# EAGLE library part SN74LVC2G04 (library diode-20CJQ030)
Ti's SN74LVC2G04 DUAL INVERTER GATE Description: This dual inverter is designed for 1.65-V to 5.5-V VCC operation. The SN74LVC2G04 performs the Boolean function Y = /A. NanoStar and NanoFree package technology is a major breakthrough in IC packaging concepts, using the die as the package. This device is fully specified for partial-power-down applications using Ioff. The Ioff circuitry disables the outputs, preventing damaging current backflow through the device when it is powered down. Features: Available in the Texas Instruments NanoStar and NanoFree Packages Supports 5-V VCC Operation Inputs Accept Voltages to 5.5 V Max tpd of 4.1 ns at 3.3 V Low Power Consumption, 10-uA Max ICC ±24-mA Output Drive at 3.3 V Typical VOLP (Output Ground Bounce) less then 0.8 V at VCC = 3.3 V, TA = 25°C Typical VOHV (Output VOH Undershoot) greater then2 V at VCC = 3.3 V, TA = 25°C Ioff Supports Partial-Power-Down Mode Operation Latch-Up Performance Exceeds 100 mA Per JESD 78, Class II ESD Protection Exceeds JESD 22 - 2000-V Human-Body Model (A114-A) - 200-V Machine Model (A115-A) - 1000-V Charged-Device Model (C101) Please send any comments to: messi@users.sourceforge.net
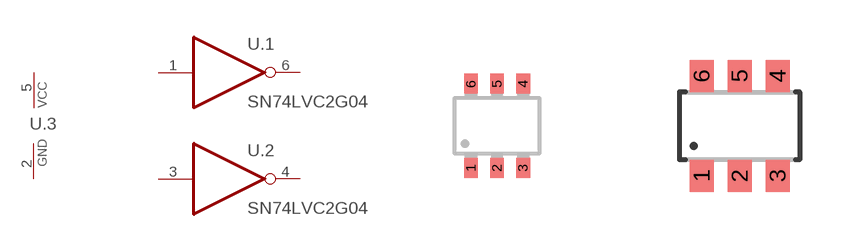
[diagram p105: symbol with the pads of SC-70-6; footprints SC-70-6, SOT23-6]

Designator prefix U; gates .1=7404 .2=7404 .3=PWR_GND

## SN74LVC2G04-DCK  [SC-70-6]
1  .1:A  in
2  .3:GND  pwr
3  .2:A  in
4  .2:Y  out
5  .3:VCC  pwr
6  .1:Y  out

## SN74LVC2G04-DBV  [SOT23-6]
Pads as for SC-70-6

## Footprint SC-70-6 (pad centres in mm)
Texas Instruments Package SC-70-6 (-DCK)
smd 0.35 x 0.5: 1 -0.65,-1.05; 2 0,-1.05; 3 0.65,-1.05; 4 0.65,1.05; 5 0,1.05; 6 -0.65,1.05

## Footprint SOT23-6 (pad centres in mm)
Small Outline Transistor 6 lead
smd 0.6 x 0.8: 1 -0.95,-1.25; 2 0,-1.25; 3 0.95,-1.25; 4 0.95,1.25; 5 0,1.25; 6 -0.95,1.25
